Omron CX-Programmer project NuevoProyecto (CX-Programmer 9.50)

# PLC NewPLC1: CP1L-E EM

## Program P14_3 (cyclic task 0)
Local symbols
Etapa_0 10.00 BOOL
Etapa_1 10.01 BOOL
Etapa_10 10.10 BOOL
Etapa_11 10.11 BOOL
Etapa_12 10.12 BOOL
Etapa_13 10.13 BOOL
Etapa_14 10.14 BOOL
Etapa_15 10.15 BOOL
Etapa_16 11.10 BOOL
Etapa_20 12.00 BOOL
Etapa_21 12.01 BOOL
Etapa_22 12.02 BOOL
Etapa_23 12.03 BOOL
Etapa_24 12.04 BOOL
Etapa_25 12.05 BOOL
Etapa_26 12.06 BOOL
FSd1 15.00 BOOL  ; Flanco Subida d1
FSd2 15.01 BOOL  ; Flanco Subida d2
KD1 100.01 BOOL
KD2 100.03 BOOL
KI1 100.00 BOOL
KI2 100.02 BOOL
a_1 0.01 BOOL
a_2 0.04 BOOL
b_1 0.02 BOOL
b_2 0.05 BOOL
c 0.07 BOOL
d_1 0.03 BOOL
d_2 0.06 BOOL
m 0.00 BOOL

### Section Sección1_GRAFCET_sincronización

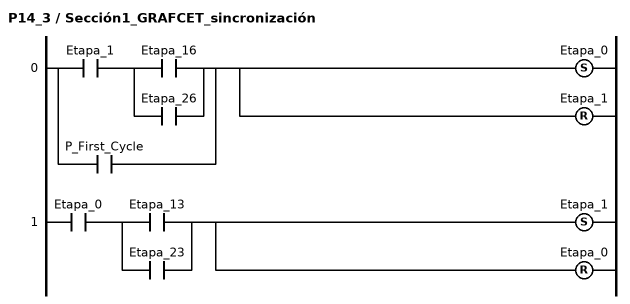
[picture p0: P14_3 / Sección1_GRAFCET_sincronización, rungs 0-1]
; rung 0
LD Etapa_1
LD Etapa_16
OR Etapa_26
ANDLD
OR P_First_Cycle
SET Etapa_0
RSET Etapa_1
; rung 1
LD Etapa_0
LD Etapa_13
OR Etapa_23
ANDLD
SET Etapa_1
RSET Etapa_0

### Section Sección2_GRAFCET_vagoneta1

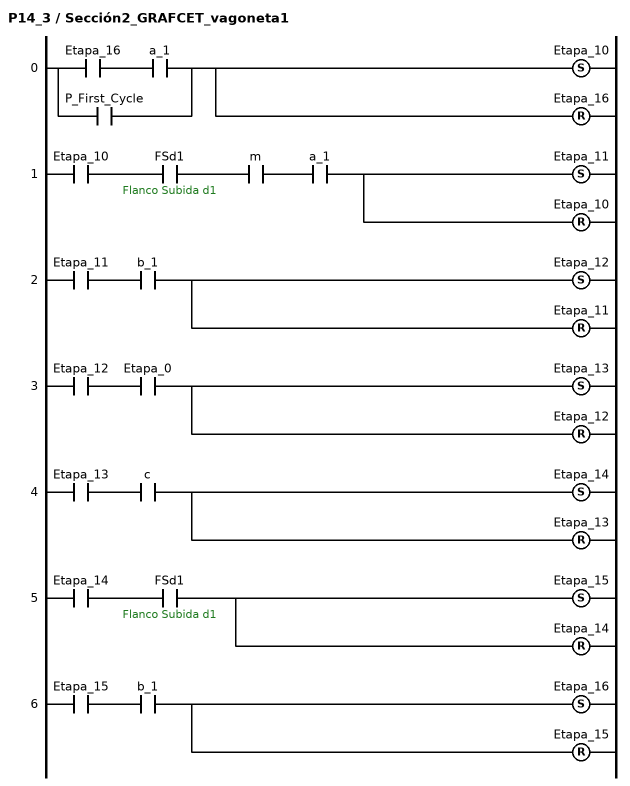
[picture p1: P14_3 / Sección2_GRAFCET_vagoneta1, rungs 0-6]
; rung 0
LD Etapa_16
AND a_1
OR P_First_Cycle
SET Etapa_10
RSET Etapa_16
; rung 1
LD Etapa_10
AND FSd1  ; Flanco Subida d1
AND m
AND a_1
SET Etapa_11
RSET Etapa_10
; rung 2
LD Etapa_11
AND b_1
SET Etapa_12
RSET Etapa_11
; rung 3
LD Etapa_12
AND Etapa_0
SET Etapa_13
RSET Etapa_12
; rung 4
LD Etapa_13
AND c
SET Etapa_14
RSET Etapa_13
; rung 5
LD Etapa_14
AND FSd1  ; Flanco Subida d1
SET Etapa_15
RSET Etapa_14
; rung 6
LD Etapa_15
AND b_1
SET Etapa_16
RSET Etapa_15

### Section Sección3_GRAFCET_vagoneta2

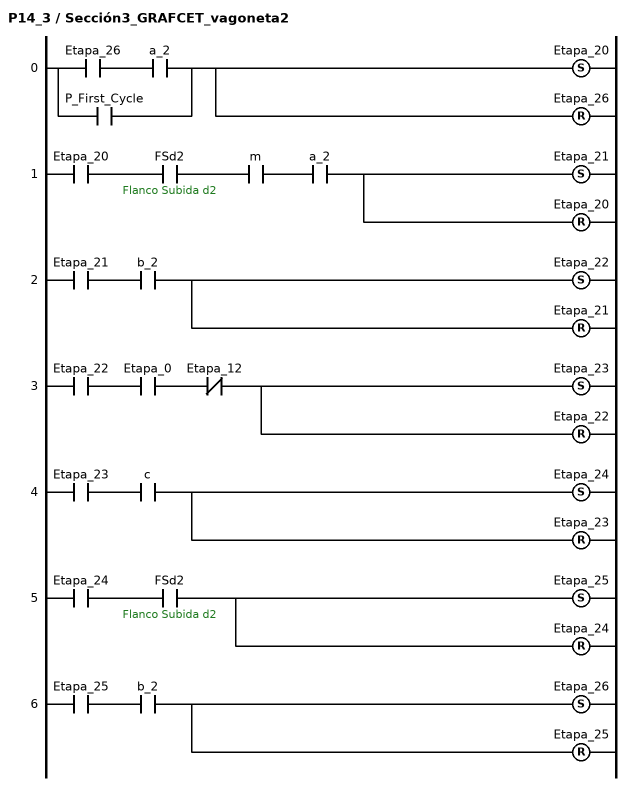
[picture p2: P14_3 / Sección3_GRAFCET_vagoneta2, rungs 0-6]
; rung 0
LD Etapa_26
AND a_2
OR P_First_Cycle
SET Etapa_20
RSET Etapa_26
; rung 1
LD Etapa_20
AND FSd2  ; Flanco Subida d2
AND m
AND a_2
SET Etapa_21
RSET Etapa_20
; rung 2
LD Etapa_21
AND b_2
SET Etapa_22
RSET Etapa_21
; rung 3
LD Etapa_22
AND Etapa_0
ANDNOT Etapa_12
SET Etapa_23
RSET Etapa_22
; rung 4
LD Etapa_23
AND c
SET Etapa_24
RSET Etapa_23
; rung 5
LD Etapa_24
AND FSd2  ; Flanco Subida d2
SET Etapa_25
RSET Etapa_24
; rung 6
LD Etapa_25
AND b_2
SET Etapa_26
RSET Etapa_25

### Section Sección4_Flancos

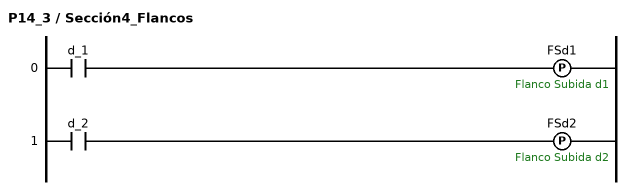
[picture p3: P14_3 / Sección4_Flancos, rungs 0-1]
; rung 0
LD d_1
DIFU(013) FSd1  ; Flanco Subida d1
; rung 1
LD d_2
DIFU(013) FSd2  ; Flanco Subida d2

### Section Sección5_Salidas

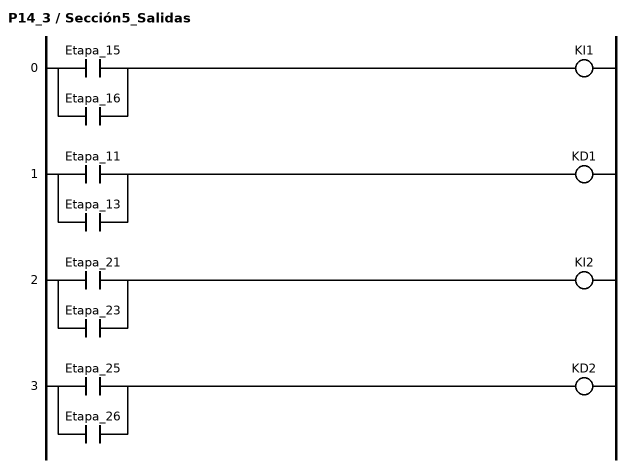
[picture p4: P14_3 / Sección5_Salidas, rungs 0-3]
; rung 0
LD Etapa_15
OR Etapa_16
OUT KI1
; rung 1
LD Etapa_11
OR Etapa_13
OUT KD1
; rung 2
LD Etapa_21
OR Etapa_23
OUT KI2
; rung 3
LD Etapa_25
OR Etapa_26
OUT KD2

### Section Sección6_END
; rung 0
END(001)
